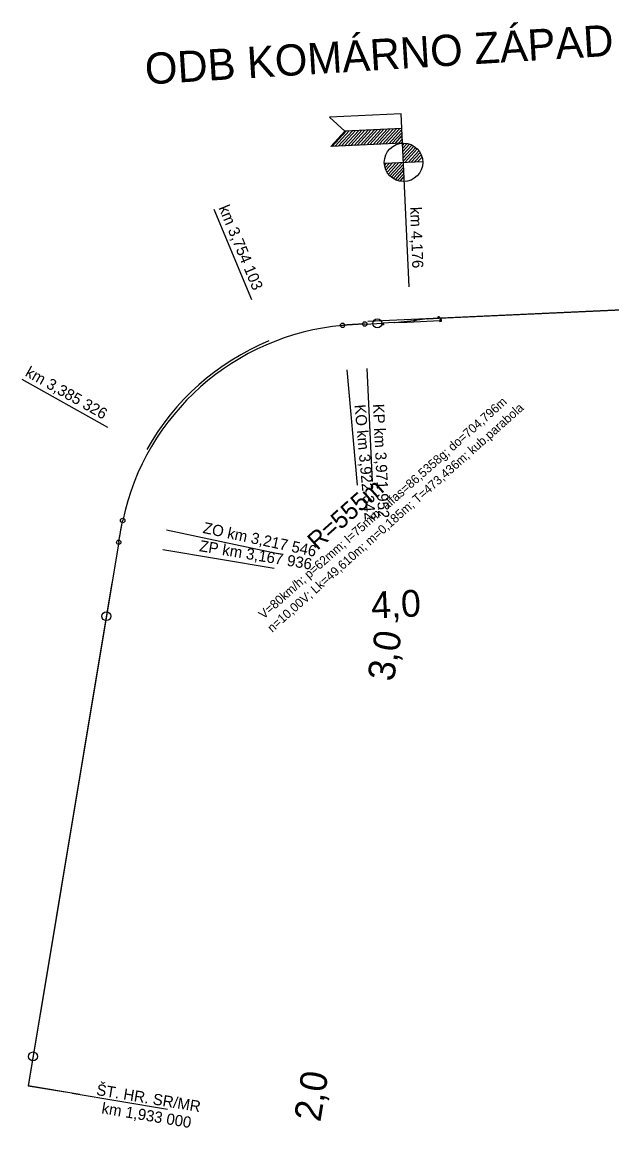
# Model space of a CAD drawing. Extents: x -504999 to -493096, y -1330712 to -1305226.
# Drawn here: x -504999 to -503678, y -1330712 to -1328234 of the extents above; entities that cross this region are included whole.
import ezdxf

# ---------------------------------------------------------------- set-up
doc = ezdxf.new("R2010")
doc.units = 0
for name, color, linetype in [('0_HM', 7, 'Continuous'), ('0_obluky', 7, 'Continuous'), ('0_os kolaje', 7, 'Continuous'), ('0_popis oblukov', 7, 'Continuous'), ('0_STANICE', 7, 'Continuous'), ('0_stanicenie oblukov', 7, 'Continuous'), ('dotyčnice', 7, 'Continuous'), ('Level 1', 7, 'Continuous'), ('PHS', 7, 'Continuous')]:
    doc.layers.add(name, color=color, linetype=linetype)

# ---------------------------------------------------------------- blocks, each defined once
blk = doc.blocks.new('RC_PRJ2')
blk.add_circle((0, 0), 1.5)
for start, end in [(0, 90), (270, 0)]:
    blk.add_arc((0, 0), 0.75, start, end)
blk = doc.blocks.new('4-30')
for p, q in [((-2, 2), (-1, 1)), ((1, 1), (2, 2)), ((-2, -2), (-1, -1)), ((1, -1), (2, -2))]:
    blk.add_line(p, q)
for points in [[(-2, 2), (-2, -2), (2, -2), (2, 2)], [(-1, 1), (-1, -1), (1, -1), (1, 1)]]:
    blk.add_lwpolyline(points, close=True)

msp = doc.modelspace()

# ---------------------------------------------------------------- linework, layer by layer
at = {"layer": '0_HM'}
for centre in [(-504203.6, -1328909.3), (-504810, -1329565.2), (-504974.4, -1330551.6)]:
    msp.add_circle(centre, 10, dxfattribs=at)
at = {"layer": '0_obluky'}
for p, q in [((-504065.8, -1328897.9), (-503123.6, -1328854.2)), ((-504231.6, -1328910.6), (-504190.9, -1328908.7)), ((-504140.1, -1328904.7), (-504116.6, -1328902)), ((-504782.4, -1329399.6), (-504985.4, -1330617.7)), ((-504869.8, -1330637), (-504985.4, -1330617.7)), ((-504886.7, -1330634.1), (-504673.2, -1330669.7))]:
    msp.add_line(p, q, dxfattribs=at)
for points in [[(-504231.6, -1328910.6), (-504232.6, -1328910.7), (-504233.7, -1328910.7), (-504234.7, -1328910.8), (-504235.7, -1328910.8), (-504236.7, -1328910.9), (-504237.7, -1328910.9), (-504238.7, -1328911), (-504239.7, -1328911), (-504240.7, -1328911.1), (-504241.7, -1328911.1), (-504242.8, -1328911.2), (-504243.8, -1328911.2), (-504244.8, -1328911.3), (-504245.8, -1328911.3), (-504246.8, -1328911.4), (-504247.8, -1328911.4), (-504248.8, -1328911.5), (-504249.8, -1328911.5), (-504250.8, -1328911.6), (-504251.9, -1328911.6), (-504252.9, -1328911.7), (-504253.9, -1328911.7), (-504254.9, -1328911.8), (-504255.9, -1328911.8), (-504256.9, -1328911.9), (-504257.9, -1328912), (-504258.9, -1328912), (-504259.9, -1328912.1), (-504261, -1328912.1), (-504262, -1328912.2), (-504263, -1328912.3), (-504264, -1328912.3), (-504265, -1328912.4), (-504266, -1328912.5), (-504267, -1328912.5), (-504268, -1328912.6), (-504269, -1328912.7), (-504270, -1328912.8), (-504271.1, -1328912.8), (-504272.1, -1328912.9), (-504273.1, -1328913), (-504274.1, -1328913.1), (-504275.1, -1328913.1), (-504276.1, -1328913.2), (-504277.1, -1328913.3), (-504278.1, -1328913.4), (-504279.1, -1328913.5), (-504280.1, -1328913.6), (-504281.2, -1328913.7)], [(-504782.4, -1329399.6), (-504782.2, -1329398.6), (-504782.1, -1329397.6), (-504781.9, -1329396.6), (-504781.7, -1329395.6), (-504781.6, -1329394.6), (-504781.4, -1329393.6), (-504781.2, -1329392.6), (-504781.1, -1329391.6), (-504780.9, -1329390.6), (-504780.7, -1329389.6), (-504780.5, -1329388.6), (-504780.4, -1329387.6), (-504780.2, -1329386.6), (-504780, -1329385.6), (-504779.9, -1329384.6), (-504779.7, -1329383.6), (-504779.5, -1329382.6), (-504779.4, -1329381.6), (-504779.2, -1329380.6), (-504779, -1329379.6), (-504778.8, -1329378.6), (-504778.7, -1329377.6), (-504778.5, -1329376.6), (-504778.3, -1329375.6), (-504778.1, -1329374.6), (-504778, -1329373.6), (-504777.8, -1329372.6), (-504777.6, -1329371.6), (-504777.4, -1329370.6), (-504777.2, -1329369.6), (-504777, -1329368.6), (-504776.9, -1329367.7), (-504776.7, -1329366.7), (-504776.5, -1329365.7), (-504776.3, -1329364.7), (-504776.1, -1329363.7), (-504775.9, -1329362.7), (-504775.7, -1329361.7), (-504775.5, -1329360.7), (-504775.3, -1329359.7), (-504775.1, -1329358.7), (-504774.9, -1329357.7), (-504774.7, -1329356.7), (-504774.5, -1329355.7), (-504774.3, -1329354.7), (-504774.1, -1329353.7), (-504773.9, -1329352.7), (-504773.7, -1329351.8), (-504773.5, -1329350.8)]]:
    msp.add_lwpolyline(points, dxfattribs=at)
for centre in [(-504281.2, -1328913.7), (-504231.6, -1328910.6), (-504773.5, -1329350.8), (-504782.4, -1329399.6)]:
    msp.add_circle(centre, 5, dxfattribs=at)
msp.add_arc((-504230.7, -1329466.4), 555, 95.2178, 167.9778, dxfattribs=at)
at = {"layer": '0_os kolaje'}
for p, q in [((-504165.8, -1328907.6), (-504190.9, -1328908.7)), ((-504190.9, -1328908.7), (-504190.9, -1328909.7)), ((-504165.1, -1328907.5), (-504136.9, -1328904.3)), ((-504165.1, -1328907.5), (-504136.7, -1328906.2)), ((-504137, -1328903.8), (-504136.8, -1328904.8)), ((-504136.9, -1328904.3), (-504119.8, -1328902.4)), ((-504136.8, -1328905.7), (-504136.7, -1328906.7)), ((-504136.7, -1328906.2), (-504062.6, -1328902.8)), ((-504091.6, -1328899.1), (-504120, -1328900.4)), ((-504119.9, -1328900.9), (-504120, -1328899.9)), ((-504119.8, -1328902.9), (-504119.9, -1328901.9)), ((-504091.6, -1328899.1), (-504119.8, -1328902.4)), ((-504090.9, -1328899.1), (-504065.8, -1328897.9)), ((-504065.8, -1328897.9), (-504065.9, -1328896.9))]:
    msp.add_line(p, q, dxfattribs=at)
for centre in [(-504165.5, -1328907.6), (-504091.3, -1328899.1)]:
    msp.add_circle(centre, 0.35, dxfattribs=at)
at = {"layer": '0_STANICE'}
for p, q in [((-504149.9, -1328439.5), (-504310.4, -1328446.9)), ((-504131.9, -1328827.5), (-504149.9, -1328439.5)), ((-504310.4, -1328446.9), (-504275.9, -1328478.4)), ((-504275.9, -1328478.4), (-504307.3, -1328512.9)), ((-504304.9, -1328512.8), (-504273.5, -1328478.3)), ((-504297.8, -1328512.4), (-504266.4, -1328477.9)), ((-504290.8, -1328512.1), (-504259.3, -1328477.6)), ((-504283.7, -1328511.8), (-504252.3, -1328477.3)), ((-504276.7, -1328511.5), (-504245.2, -1328476.9)), ((-504148.4, -1328472.4), (-504275.9, -1328478.4)), ((-504269.6, -1328511.1), (-504238.1, -1328476.6)), ((-504262.5, -1328510.8), (-504231.1, -1328476.3)), ((-504255.5, -1328510.5), (-504224, -1328476)), ((-504248.4, -1328510.1), (-504217, -1328475.6)), ((-504241.3, -1328509.8), (-504209.9, -1328475.3)), ((-504234.3, -1328509.5), (-504202.8, -1328475)), ((-504227.2, -1328509.2), (-504195.8, -1328474.6)), ((-504220.1, -1328508.8), (-504188.7, -1328474.3)), ((-504213.1, -1328508.5), (-504181.6, -1328474)), ((-504206, -1328508.2), (-504174.6, -1328473.7)), ((-504199, -1328507.8), (-504167.5, -1328473.3)), ((-504191.9, -1328507.5), (-504160.4, -1328473)), ((-504184.8, -1328507.2), (-504153.4, -1328472.7)), ((-504177.8, -1328506.9), (-504148.3, -1328474.5)), ((-504170.7, -1328506.5), (-504147.9, -1328481.5)), ((-504163.6, -1328506.2), (-504147.6, -1328488.6)), ((-504163.6, -1328506.2), (-504147.6, -1328488.6)), ((-504146.8, -1328505.4), (-504307.3, -1328512.9)), ((-504156.6, -1328505.9), (-504147.3, -1328495.7)), ((-504156.6, -1328505.9), (-504147.3, -1328495.7)), ((-504149.5, -1328505.6), (-504146.9, -1328502.7)), ((-504149.5, -1328505.6), (-504146.9, -1328502.7)), ((-504146.6, -1328509.8), (-504142.6, -1328505.4)), ((-504146.3, -1328516.9), (-504136.6, -1328506.2)), ((-504146, -1328523.9), (-504131.1, -1328507.6)), ((-504145.6, -1328531), (-504126.2, -1328509.6)), ((-504145.3, -1328538.1), (-504121.7, -1328512.1)), ((-504145, -1328545.1), (-504117.6, -1328515.1)), ((-504141, -1328548.2), (-504113.9, -1328518.5)), ((-504134, -1328547.9), (-504110.6, -1328522.3)), ((-504126.9, -1328547.6), (-504107.8, -1328526.6)), ((-504119.9, -1328547.2), (-504105.3, -1328531.3)), ((-504112.8, -1328546.9), (-504103.4, -1328536.7)), ((-504187.8, -1328550.4), (-504101.9, -1328546.4)), ((-504183.4, -1328550.3), (-504187.4, -1328554.6)), ((-504176.4, -1328549.9), (-504186.1, -1328560.6)), ((-504169.3, -1328549.6), (-504184.1, -1328565.9)), ((-504162.2, -1328549.2), (-504181.7, -1328570.6)), ((-504178.8, -1328574.8), (-504155.2, -1328548.9)), ((-504175.5, -1328578.6), (-504148.1, -1328548.6)), ((-504171.8, -1328581.9), (-504144.7, -1328552.2)), ((-504167.7, -1328584.9), (-504144.3, -1328559.2)), ((-504163.1, -1328587.3), (-504144, -1328566.3)), ((-504158.2, -1328589.3), (-504143.7, -1328573.4)), ((-504152.7, -1328590.7), (-504143.3, -1328580.4))]:
    msp.add_line(p, q, dxfattribs=at)
msp.add_circle((-504144.8, -1328548.4), 43, dxfattribs=at)
at = {"layer": '0_stanicenie oblukov'}
for p, q in [((-503131, -1328854.6), (-504225, -1328905.3)), ((-504272.1, -1329013.3), (-504248.5, -1329271.6)), ((-504227, -1329010.5), (-504215.3, -1329263.5)), ((-504675.7, -1329371.6), (-504425.9, -1329424.8)), ((-504683.7, -1329416), (-504434.5, -1329457.5))]:
    msp.add_line(p, q, dxfattribs=at)
at = {"layer": 'dotyčnice'}
msp.add_line((-504797.6, -1329490.7), (-504985.4, -1330617.7), dxfattribs=at)
at = {"layer": 'Level 1'}
for p, q in [((-503195.9, -1328857.6), (-504117.5, -1328900.3)), ((-504797.6, -1329490.7), (-504827.9, -1329672.5)), ((-504985.4, -1330617.7), (-504902.5, -1330630.9))]:
    msp.add_line(p, q, dxfattribs=at)
msp.add_lwpolyline([(-504827.9, -1329672.5), (-504911.3, -1330174.3), (-504958.6, -1330457.3)], dxfattribs=at)
at = {"layer": 'PHS'}
for p, q in [((-504484.5, -1328856.1), (-504568.5, -1328654.2)), ((-504806.9, -1329142.5), (-504998.6, -1329034.6))]:
    msp.add_line(p, q, dxfattribs=at)
msp.add_arc((-504230.7, -1329466.4), 561, 112.586, 150.657, dxfattribs=at)

# ---------------------------------------------------------------- block references
at = {"layer": '0_os kolaje'}
for name, p, rotation in [('RC_PRJ2', (-504190.8, -1328911.2), -177.34328617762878), ('RC_PRJ2', (-504065.9, -1328895.4), -177.34328617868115), ('4-30', (-504061.8, -1328902.7), 2.656713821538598)]:
    msp.add_blockref(name, p, dxfattribs=dict(at, rotation=rotation))

# ---------------------------------------------------------------- texts
at = {"layer": '0_HM'}
for s, rotation, p in [('4,0', 2.6567, (-504216.1, -1329570.6)), ('3,0', 80.5389, (-504166.9, -1329713.2)), ('2,0', 80.5389, (-504331.2, -1330699.9))]:
    msp.add_text(s, height=60, rotation=rotation, dxfattribs=at).set_placement(p)
at = {"layer": '0_obluky'}
for s, p in [('ŠT. HR. SR/MR', (-504833.9, -1330637.7)), ('km 1,933 000', (-504822, -1330678.9))]:
    msp.add_text(s, height=25, rotation=350.5389, dxfattribs=at).set_placement(p)
at = {"layer": '0_popis oblukov'}
for s, height, p in [('V=80km/h; p=62mm; I=75mm; alfas=86,5358g; do=704,796m', 20, (-504458, -1329572.7)), ('n=10,00V; Lk=49,610m; m=0,185m; T=473,436m; kub.parabola', 20, (-504438.8, -1329602.5)), ('R=555m', 40, (-504337.9, -1329419.3))]:
    msp.add_text(s, height=height, rotation=41.5978, dxfattribs=at).set_placement(p)
at = {"layer": '0_STANICE'}
for s, height, rotation, p in [('ODB KOMÁRNO ZÁPAD', 70, 3.5435, (-504721.6, -1328374.2)), ('km 4,176', 25, 271.9708, (-504129.9, -1328648.7))]:
    msp.add_text(s, height=height, rotation=rotation, dxfattribs=at).set_placement(p)
at = {"layer": '0_stanicenie oblukov'}
for s, rotation, p in [('KO km 3,922 342', 275.2178, (-504254.8, -1329092)), ('KP km 3,971 952', 272.6567, (-504213.3, -1329090)), ('ZO km 3,217 546', 347.9778, (-504595.4, -1329378.5)), ('ZP km 3,167 936', 350.5389, (-504603.2, -1329419.3))]:
    msp.add_text(s, height=25, rotation=rotation, dxfattribs=at).set_placement(p)
at = {"layer": 'PHS'}
for s, rotation, p in [('km 3,754 103', 292.586, (-504559.3, -1328650.3)), ('km 3,385 326', 330.657, (-504993.7, -1329025.9))]:
    msp.add_text(s, height=25, rotation=rotation, dxfattribs=at).set_placement(p)

doc.saveas('drawing.dxf')
